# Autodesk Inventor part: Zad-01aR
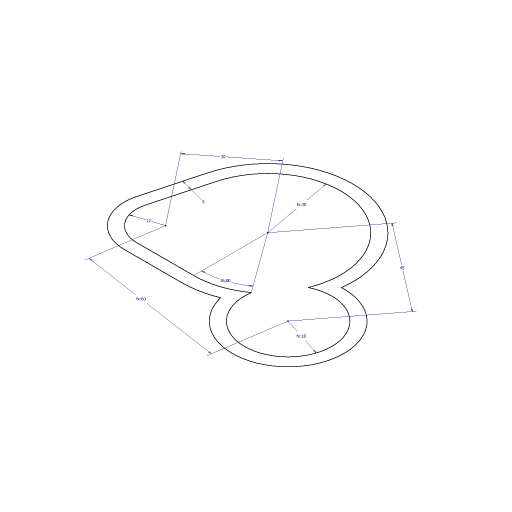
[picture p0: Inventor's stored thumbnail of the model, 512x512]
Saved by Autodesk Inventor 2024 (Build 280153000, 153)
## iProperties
Company: ATC
Shininess: 20.0
Length Units: 11269
Angle Units: 11279
Time Units: 11290
Mass Units: 11283
Angle Display Precision: 2
Created: 2023-03
Part Number: Zad-01aR
Document SubType Name: Modeling
Designer: Andrzej Jaskulski
Density: 1 g/cm^3
Material: Kurs-AJ
Appearance: Kurs-AJ
Checked By: A.J.
Engr Approved By: Andrzej Jaskulski
Mfg Approved By: Andrzej Jaskulski
Authority: A.J.
Density: 0.0
Volumn: 0.0
Area: 0.0
PropertySet Name: Model Information
Control State: 0
Master: False
Checked Out: False
Title: A.J.: Kurs R2024-MEP
Author: Andrzej Jaskulski
Revision Number: 1/24
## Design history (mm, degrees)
sketch "Uszczelka"
  geometry: L1 (-1.588, 13.116)-(4.644, 36.293); L2 (10, -2)-(33.615, -2); L3 (-0.185, 37.591)-(-6.417, 14.414); L4 (10, -7)-(33.615, -7); A1 r 18 centre (69.343, 1.144) between (51.544, 3.825) and (61.454, 17.323); A2 r 12 centre (10, 10) between (-1.588, 13.116) and (10, -2); A3 r 30.503 centre (33.615, 28.503) between (33.615, -2) and (51.544, 3.825); A4 r 30 centre (33.615, 28.503) between (61.454, 17.323) and (4.644, 36.293); A5 r 17 centre (10, 10) between (-6.417, 14.414) and (10, -7); A6 r 35.503 centre (33.615, 28.503) between (33.615, -7) and (47.014, -4.374); A7 r 23 centre (69.343, 1.144) between (47.014, -4.374) and (68.339, 24.122); A8 r 35 centre (33.615, 28.503) between (68.339, 24.122) and (-0.185, 37.591)
  constraints: 16 point on circle, 8 centre point, 8 end point, 4 tangent, 1 horizontal, 6 other
  dimensions: "d0" = 12 radius of A2; "d1" = 30 distance of A3.centre A2.centre; "d2" = 45 distance of A1.centre A3.centre; "d3" = 18 radius of A1 (= 1.5 x d0); "d4" = 30 radius of A4 (= d1); "d5" = 60 distance of A1.centre A2.centre (= 2 x d1); "d6" = 5 distance between parallel lines of L3 L1; "d7" = 36 deg dimension on A3.centre A1.start L2.end
node "Korpusy bryłowe"
node "Korpusy powierzchniowe"
